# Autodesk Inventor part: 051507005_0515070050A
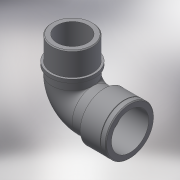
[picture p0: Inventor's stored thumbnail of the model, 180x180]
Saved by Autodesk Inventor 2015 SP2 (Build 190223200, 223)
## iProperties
Created: 2017-05
Part Number: 051507005_0515070050A
Material: Generic
Description: PLASSON 90° THREADED ELBOW MALE-FEMALE 1/2"-1/2"
Document SubType Name: Modeling
Designer: KIM
Mass: 10.7057 g
Surface Area: 87.3624 cm^2
Volume: 10.7057 cm^3
Density: 1 g/cm^3
Appearance: Default
Author: KIM
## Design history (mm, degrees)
derived "051507.ipt"
feature "Solid1::051507.ipt"
tag "TaggingFeature1"
body "Solid1"
other parameters: "d0" = 36, "d1" = 36, "d2" = 0.5, "d3" = 0.5, "d4" = 24.2203, "d5" = 18.631, "d6" = 17, "d7" = 120 deg, "d8" = 20.4, "d9" = 3.4, "d10" = 20.58726, "d11" = 20.955, "d12" = 16, "d13" = 20.58726, "d14" = 15.71625, "d15" = 18.4, "d16" = 15.71625, "d19" = 0.4191, "d23" = 19.2, "d24" = 23.0505, "d25" = 0, "d26" = 0, "d27" = 17.6, "R_" = 20.955, "Rp_" = 18.631, "A_" = 36, "A_1" = 36, "l_" = 16, "l_1" = 17
